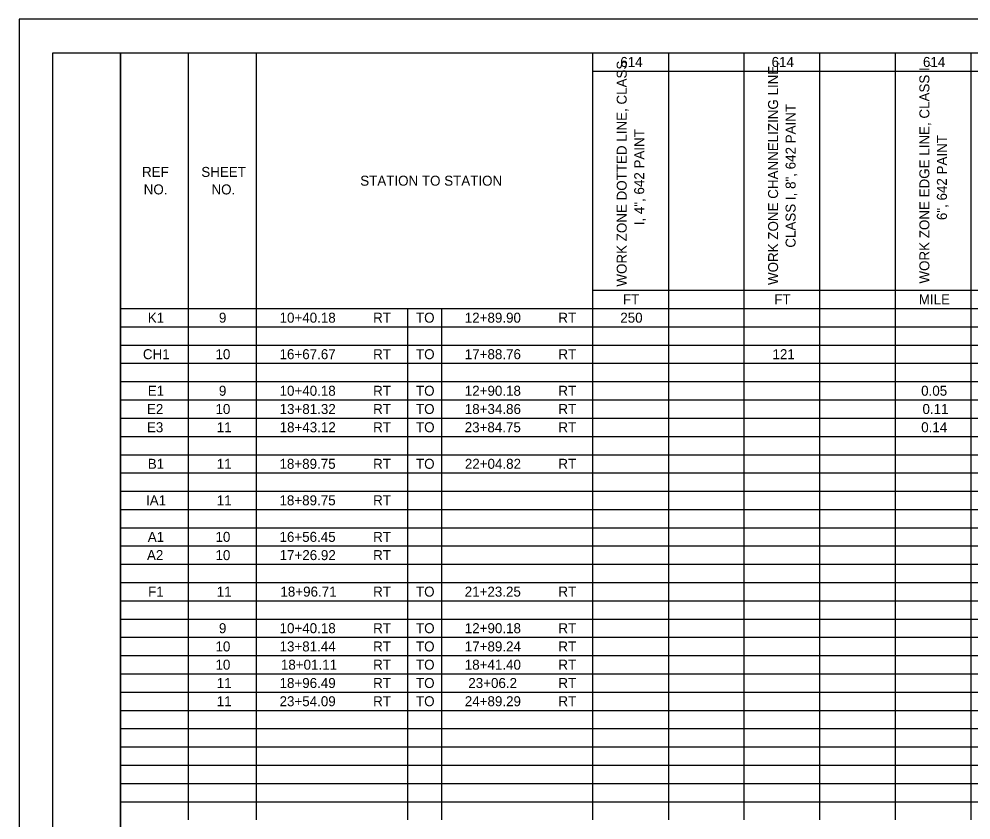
# Model space of a CAD drawing. Extents: x 0 to 34, y 0 to 22.
# Drawn here: x 0 to 14.09, y 10.15 to 22 of the extents above; entities that cross this region are included whole.
import ezdxf

# ---------------------------------------------------------------- set-up
doc = ezdxf.new("R2010")
doc.units = 0
for name, color, linetype in [('Default', 7, 'Continuous'), ('SH_Border', 7, 'Continuous'), ('SH_Cut_Line', 7, 'Continuous')]:
    doc.layers.add(name, color=color, linetype=linetype)

msp = doc.modelspace()

# ---------------------------------------------------------------- linework, layer by layer
at = {"layer": 'Default'}
for p, q in [((1.5, 21.5), (5.747, 21.5)), ((1.5, 21.5), (1.5, 21.23)), ((2.504, 21.5), (2.504, 21.23)), ((3.508, 21.5), (3.508, 21.23)), ((5.747, 21.5), (6.249, 21.5)), ((6.249, 21.5), (7.716, 21.5)), ((7.716, 21.5), (10.727, 21.5)), ((8.488, 21.5), (8.488, 21.23)), ((9.608, 21.5), (9.608, 21.23)), ((10.727, 21.5), (11.847, 21.5)), ((10.727, 21.5), (10.727, 21.23)), ((11.847, 21.5), (14.086, 21.5)), ((11.847, 21.5), (11.847, 21.23)), ((12.966, 21.5), (12.966, 21.23)), ((14.086, 21.5), (15.206, 21.5)), ((14.086, 21.5), (14.086, 21.23)), ((1.5, 21.23), (1.5, 20.959)), ((2.504, 21.23), (2.504, 20.959)), ((3.508, 21.23), (3.508, 20.959)), ((8.488, 21.23), (10.727, 21.23)), ((8.488, 21.23), (8.488, 20.959)), ((9.608, 21.23), (9.608, 20.959)), ((10.727, 21.23), (11.847, 21.23)), ((10.727, 21.23), (10.727, 20.959)), ((11.847, 21.23), (14.086, 21.23)), ((11.847, 21.23), (11.847, 20.959)), ((12.966, 21.23), (12.966, 20.959)), ((14.086, 21.23), (15.206, 21.23)), ((14.086, 21.23), (14.086, 20.959)), ((1.5, 20.959), (1.5, 20.689)), ((2.504, 20.959), (2.504, 20.689)), ((3.508, 20.959), (3.508, 20.689)), ((8.488, 20.959), (8.488, 20.689)), ((9.608, 20.959), (9.608, 20.689)), ((10.727, 20.959), (10.727, 20.689)), ((11.847, 20.959), (11.847, 20.689)), ((12.966, 20.959), (12.966, 20.689)), ((14.086, 20.959), (14.086, 20.689)), ((1.5, 20.689), (1.5, 20.419)), ((2.504, 20.689), (2.504, 20.419)), ((3.508, 20.689), (3.508, 20.419)), ((8.488, 20.689), (8.488, 20.419)), ((9.608, 20.689), (9.608, 20.419)), ((10.727, 20.689), (10.727, 20.419)), ((11.847, 20.689), (11.847, 20.419)), ((12.966, 20.689), (12.966, 20.419)), ((14.086, 20.689), (14.086, 20.419)), ((1.5, 20.419), (1.5, 20.149)), ((2.504, 20.419), (2.504, 20.149)), ((3.508, 20.419), (3.508, 20.149)), ((8.488, 20.419), (8.488, 20.149)), ((9.608, 20.419), (9.608, 20.149)), ((10.727, 20.419), (10.727, 20.149)), ((11.847, 20.419), (11.847, 20.149)), ((12.966, 20.419), (12.966, 20.149)), ((14.086, 20.419), (14.086, 20.149)), ((1.5, 20.149), (1.5, 19.878)), ((2.504, 20.149), (2.504, 19.878)), ((3.508, 20.149), (3.508, 19.878)), ((8.488, 20.149), (8.488, 19.878)), ((9.608, 20.149), (9.608, 19.878)), ((10.727, 20.149), (10.727, 19.878)), ((11.847, 20.149), (11.847, 19.878)), ((12.966, 20.149), (12.966, 19.878)), ((14.086, 20.149), (14.086, 19.878)), ((1.5, 19.878), (1.5, 19.608)), ((2.504, 19.878), (2.504, 19.608)), ((3.508, 19.878), (3.508, 19.608)), ((8.488, 19.878), (8.488, 19.608)), ((9.608, 19.878), (9.608, 19.608)), ((10.727, 19.878), (10.727, 19.608)), ((11.847, 19.878), (11.847, 19.608)), ((12.966, 19.878), (12.966, 19.608)), ((14.086, 19.878), (14.086, 19.608)), ((1.5, 19.608), (1.5, 19.068)), ((2.504, 19.608), (2.504, 19.068)), ((3.508, 19.608), (3.508, 19.068)), ((8.488, 19.608), (8.488, 19.068)), ((9.608, 19.608), (9.608, 19.068)), ((10.727, 19.608), (10.727, 19.068)), ((11.847, 19.608), (11.847, 19.068)), ((12.966, 19.608), (12.966, 19.068)), ((14.086, 19.608), (14.086, 19.068)), ((1.5, 19.068), (1.5, 18.257)), ((2.504, 19.068), (2.504, 18.257)), ((3.508, 19.068), (3.508, 18.257)), ((8.488, 19.068), (8.488, 18.257)), ((9.608, 19.068), (9.608, 18.257)), ((10.727, 19.068), (10.727, 18.257)), ((11.847, 19.068), (11.847, 18.257)), ((12.966, 19.068), (12.966, 18.257)), ((14.086, 19.068), (14.086, 18.257)), ((1.5, 18.257), (1.5, 17.987)), ((2.504, 18.257), (2.504, 17.987)), ((3.508, 18.257), (3.508, 17.987)), ((8.488, 18.257), (8.488, 17.987)), ((9.608, 18.257), (9.608, 17.987)), ((10.727, 18.257), (10.727, 17.987)), ((11.847, 18.257), (11.847, 17.987)), ((12.966, 18.257), (12.966, 17.987)), ((14.086, 18.257), (14.086, 17.987)), ((1.5, 17.987), (1.5, 17.446)), ((2.504, 17.987), (2.504, 17.446)), ((3.508, 17.987), (3.508, 17.446)), ((8.488, 17.987), (10.727, 17.987)), ((8.488, 17.987), (8.488, 17.446)), ((9.608, 17.987), (9.608, 17.446)), ((10.727, 17.987), (11.847, 17.987)), ((10.727, 17.987), (10.727, 17.446)), ((11.847, 17.987), (14.086, 17.987)), ((11.847, 17.987), (11.847, 17.446)), ((12.966, 17.987), (12.966, 17.446)), ((14.086, 17.987), (15.206, 17.987)), ((14.086, 17.987), (14.086, 17.446)), ((1.5, 17.716), (5.747, 17.716)), ((5.747, 17.716), (6.249, 17.716)), ((5.747, 17.716), (5.747, 17.446)), ((6.249, 17.716), (7.716, 17.716)), ((6.249, 17.716), (6.249, 17.446)), ((7.716, 17.716), (10.727, 17.716)), ((10.727, 17.716), (11.847, 17.716)), ((11.847, 17.716), (14.086, 17.716)), ((14.086, 17.716), (15.206, 17.716)), ((1.5, 17.446), (5.747, 17.446)), ((1.5, 17.446), (1.5, 17.176)), ((2.504, 17.446), (2.504, 17.176)), ((3.508, 17.446), (3.508, 17.176)), ((5.747, 17.446), (6.249, 17.446)), ((5.747, 17.446), (5.747, 17.176)), ((6.249, 17.446), (7.716, 17.446)), ((6.249, 17.446), (6.249, 17.176)), ((7.716, 17.446), (10.727, 17.446)), ((8.488, 17.446), (8.488, 17.176)), ((9.608, 17.446), (9.608, 17.176)), ((10.727, 17.446), (11.847, 17.446)), ((10.727, 17.446), (10.727, 17.176)), ((11.847, 17.446), (14.086, 17.446)), ((11.847, 17.446), (11.847, 17.176)), ((12.966, 17.446), (12.966, 17.176)), ((14.086, 17.446), (15.206, 17.446)), ((14.086, 17.446), (14.086, 17.176)), ((1.5, 17.176), (5.747, 17.176)), ((1.5, 17.176), (1.5, 16.095)), ((2.504, 17.176), (2.504, 16.095)), ((3.508, 17.176), (3.508, 16.095)), ((5.747, 17.176), (6.249, 17.176)), ((5.747, 17.176), (5.747, 16.095)), ((6.249, 17.176), (7.716, 17.176)), ((6.249, 17.176), (6.249, 16.095)), ((7.716, 17.176), (10.727, 17.176)), ((8.488, 17.176), (8.488, 16.095)), ((9.608, 17.176), (9.608, 16.095)), ((10.727, 17.176), (11.847, 17.176)), ((10.727, 17.176), (10.727, 16.095)), ((11.847, 17.176), (14.086, 17.176)), ((11.847, 17.176), (11.847, 16.095)), ((12.966, 17.176), (12.966, 16.095)), ((14.086, 17.176), (15.206, 17.176)), ((14.086, 17.176), (14.086, 16.095)), ((1.5, 16.906), (5.747, 16.906)), ((5.747, 16.906), (6.249, 16.906)), ((6.249, 16.906), (7.716, 16.906)), ((7.716, 16.906), (10.727, 16.906)), ((10.727, 16.906), (11.847, 16.906)), ((11.847, 16.906), (14.086, 16.906)), ((14.086, 16.906), (15.206, 16.906)), ((1.5, 16.635), (5.747, 16.635)), ((5.747, 16.635), (6.249, 16.635)), ((6.249, 16.635), (7.716, 16.635)), ((7.716, 16.635), (10.727, 16.635)), ((10.727, 16.635), (11.847, 16.635)), ((11.847, 16.635), (14.086, 16.635)), ((14.086, 16.635), (15.206, 16.635)), ((1.5, 16.365), (5.747, 16.365)), ((5.747, 16.365), (6.249, 16.365)), ((6.249, 16.365), (7.716, 16.365)), ((7.716, 16.365), (10.727, 16.365)), ((10.727, 16.365), (11.847, 16.365)), ((11.847, 16.365), (14.086, 16.365)), ((14.086, 16.365), (15.206, 16.365)), ((1.5, 16.095), (5.747, 16.095)), ((1.5, 16.095), (1.5, 15.825)), ((2.504, 16.095), (2.504, 15.825)), ((3.508, 16.095), (3.508, 15.825)), ((5.747, 16.095), (6.249, 16.095)), ((5.747, 16.095), (5.747, 15.825)), ((6.249, 16.095), (7.716, 16.095)), ((6.249, 16.095), (6.249, 15.825)), ((7.716, 16.095), (10.727, 16.095)), ((8.488, 16.095), (8.488, 15.825)), ((9.608, 16.095), (9.608, 15.825)), ((10.727, 16.095), (11.847, 16.095)), ((10.727, 16.095), (10.727, 15.825)), ((11.847, 16.095), (14.086, 16.095)), ((11.847, 16.095), (11.847, 15.825)), ((12.966, 16.095), (12.966, 15.825)), ((14.086, 16.095), (15.206, 16.095)), ((14.086, 16.095), (14.086, 15.825)), ((1.5, 15.825), (5.747, 15.825)), ((1.5, 15.825), (1.5, 15.284)), ((2.504, 15.825), (2.504, 15.284)), ((3.508, 15.825), (3.508, 15.284)), ((5.747, 15.825), (6.249, 15.825)), ((5.747, 15.825), (5.747, 15.284)), ((6.249, 15.825), (7.716, 15.825)), ((6.249, 15.825), (6.249, 15.284)), ((7.716, 15.825), (10.727, 15.825)), ((8.488, 15.825), (8.488, 15.284)), ((9.608, 15.825), (9.608, 15.284)), ((10.727, 15.825), (11.847, 15.825)), ((10.727, 15.825), (10.727, 15.284)), ((11.847, 15.825), (14.086, 15.825)), ((11.847, 15.825), (11.847, 15.284)), ((12.966, 15.825), (12.966, 15.284)), ((14.086, 15.825), (15.206, 15.825)), ((14.086, 15.825), (14.086, 15.284)), ((1.5, 15.554), (5.747, 15.554)), ((5.747, 15.554), (6.249, 15.554)), ((6.249, 15.554), (7.716, 15.554)), ((7.716, 15.554), (10.727, 15.554)), ((10.727, 15.554), (11.847, 15.554)), ((11.847, 15.554), (14.086, 15.554)), ((14.086, 15.554), (15.206, 15.554)), ((1.5, 15.284), (5.747, 15.284)), ((1.5, 15.284), (1.5, 14.744)), ((2.504, 15.284), (2.504, 14.744)), ((3.508, 15.284), (3.508, 14.744)), ((5.747, 15.284), (6.249, 15.284)), ((5.747, 15.284), (5.747, 14.744)), ((6.249, 15.284), (7.716, 15.284)), ((6.249, 15.284), (6.249, 14.744)), ((7.716, 15.284), (10.727, 15.284)), ((8.488, 15.284), (8.488, 14.744)), ((9.608, 15.284), (9.608, 14.744)), ((10.727, 15.284), (11.847, 15.284)), ((10.727, 15.284), (10.727, 14.744)), ((11.847, 15.284), (14.086, 15.284)), ((11.847, 15.284), (11.847, 14.744)), ((12.966, 15.284), (12.966, 14.744)), ((14.086, 15.284), (15.206, 15.284)), ((14.086, 15.284), (14.086, 14.744)), ((1.5, 15.014), (5.747, 15.014)), ((5.747, 15.014), (6.249, 15.014)), ((6.249, 15.014), (7.716, 15.014)), ((7.716, 15.014), (10.727, 15.014)), ((10.727, 15.014), (11.847, 15.014)), ((11.847, 15.014), (14.086, 15.014)), ((14.086, 15.014), (15.206, 15.014)), ((1.5, 14.744), (5.747, 14.744)), ((1.5, 14.744), (1.5, 14.473)), ((2.504, 14.744), (2.504, 14.473)), ((3.508, 14.744), (3.508, 14.473)), ((5.747, 14.744), (6.249, 14.744)), ((5.747, 14.744), (5.747, 14.473)), ((6.249, 14.744), (7.716, 14.744)), ((6.249, 14.744), (6.249, 14.473)), ((7.716, 14.744), (10.727, 14.744)), ((8.488, 14.744), (8.488, 14.473)), ((9.608, 14.744), (9.608, 14.473)), ((10.727, 14.744), (11.847, 14.744)), ((10.727, 14.744), (10.727, 14.473)), ((11.847, 14.744), (14.086, 14.744)), ((11.847, 14.744), (11.847, 14.473)), ((12.966, 14.744), (12.966, 14.473)), ((14.086, 14.744), (15.206, 14.744)), ((14.086, 14.744), (14.086, 14.473)), ((1.5, 14.473), (5.747, 14.473)), ((1.5, 14.473), (1.5, 13.933)), ((2.504, 14.473), (2.504, 13.933)), ((3.508, 14.473), (3.508, 13.933)), ((5.747, 14.473), (6.249, 14.473)), ((5.747, 14.473), (5.747, 13.933)), ((6.249, 14.473), (7.716, 14.473)), ((6.249, 14.473), (6.249, 13.933)), ((7.716, 14.473), (10.727, 14.473)), ((8.488, 14.473), (8.488, 13.933)), ((9.608, 14.473), (9.608, 13.933)), ((10.727, 14.473), (11.847, 14.473)), ((10.727, 14.473), (10.727, 13.933)), ((11.847, 14.473), (14.086, 14.473)), ((11.847, 14.473), (11.847, 13.933)), ((12.966, 14.473), (12.966, 13.933)), ((14.086, 14.473), (15.206, 14.473)), ((14.086, 14.473), (14.086, 13.933)), ((1.5, 14.203), (5.747, 14.203)), ((5.747, 14.203), (6.249, 14.203)), ((6.249, 14.203), (7.716, 14.203)), ((7.716, 14.203), (10.727, 14.203)), ((10.727, 14.203), (11.847, 14.203)), ((11.847, 14.203), (14.086, 14.203)), ((14.086, 14.203), (15.206, 14.203)), ((1.5, 13.933), (5.747, 13.933)), ((1.5, 13.933), (1.5, 13.663)), ((2.504, 13.933), (2.504, 13.663)), ((3.508, 13.933), (3.508, 13.663)), ((5.747, 13.933), (6.249, 13.933)), ((5.747, 13.933), (5.747, 13.663)), ((6.249, 13.933), (7.716, 13.933)), ((6.249, 13.933), (6.249, 13.663)), ((7.716, 13.933), (10.727, 13.933)), ((8.488, 13.933), (8.488, 13.663)), ((9.608, 13.933), (9.608, 13.663)), ((10.727, 13.933), (11.847, 13.933)), ((10.727, 13.933), (10.727, 13.663)), ((11.847, 13.933), (14.086, 13.933)), ((11.847, 13.933), (11.847, 13.663)), ((12.966, 13.933), (12.966, 13.663)), ((14.086, 13.933), (15.206, 13.933)), ((14.086, 13.933), (14.086, 13.663)), ((1.5, 13.663), (5.747, 13.663)), ((1.5, 13.663), (1.5, 12.852)), ((2.504, 13.663), (2.504, 12.852)), ((3.508, 13.663), (3.508, 12.852)), ((5.747, 13.663), (6.249, 13.663)), ((5.747, 13.663), (5.747, 12.852)), ((6.249, 13.663), (7.716, 13.663)), ((6.249, 13.663), (6.249, 12.852)), ((7.716, 13.663), (10.727, 13.663)), ((8.488, 13.663), (8.488, 12.852)), ((9.608, 13.663), (9.608, 12.852)), ((10.727, 13.663), (11.847, 13.663)), ((10.727, 13.663), (10.727, 12.852)), ((11.847, 13.663), (14.086, 13.663)), ((11.847, 13.663), (11.847, 12.852)), ((12.966, 13.663), (12.966, 12.852)), ((14.086, 13.663), (15.206, 13.663)), ((14.086, 13.663), (14.086, 12.852)), ((1.5, 13.392), (5.747, 13.392)), ((5.747, 13.392), (6.249, 13.392)), ((6.249, 13.392), (7.716, 13.392)), ((7.716, 13.392), (10.727, 13.392)), ((10.727, 13.392), (11.847, 13.392)), ((11.847, 13.392), (14.086, 13.392)), ((14.086, 13.392), (15.206, 13.392)), ((1.5, 13.122), (5.747, 13.122)), ((5.747, 13.122), (6.249, 13.122)), ((6.249, 13.122), (7.716, 13.122)), ((7.716, 13.122), (10.727, 13.122)), ((10.727, 13.122), (11.847, 13.122)), ((11.847, 13.122), (14.086, 13.122)), ((14.086, 13.122), (15.206, 13.122)), ((1.5, 12.852), (5.747, 12.852)), ((1.5, 12.852), (1.5, 12.311)), ((2.504, 12.852), (2.504, 12.311)), ((3.508, 12.852), (3.508, 12.311)), ((5.747, 12.852), (6.249, 12.852)), ((5.747, 12.852), (5.747, 12.311)), ((6.249, 12.852), (7.716, 12.852)), ((6.249, 12.852), (6.249, 12.311)), ((7.716, 12.852), (10.727, 12.852)), ((8.488, 12.852), (8.488, 12.311)), ((9.608, 12.852), (9.608, 12.311)), ((10.727, 12.852), (11.847, 12.852)), ((10.727, 12.852), (10.727, 12.311)), ((11.847, 12.852), (14.086, 12.852)), ((11.847, 12.852), (11.847, 12.311)), ((12.966, 12.852), (12.966, 12.311)), ((14.086, 12.852), (15.206, 12.852)), ((14.086, 12.852), (14.086, 12.311)), ((1.5, 12.582), (5.747, 12.582)), ((5.747, 12.582), (6.249, 12.582)), ((6.249, 12.582), (7.716, 12.582)), ((7.716, 12.582), (10.727, 12.582)), ((10.727, 12.582), (11.847, 12.582)), ((11.847, 12.582), (14.086, 12.582)), ((14.086, 12.582), (15.206, 12.582)), ((1.5, 12.311), (5.747, 12.311)), ((1.5, 12.311), (1.5, 11.501)), ((2.504, 12.311), (2.504, 11.501)), ((3.508, 12.311), (3.508, 11.501)), ((5.747, 12.311), (6.249, 12.311)), ((5.747, 12.311), (5.747, 11.501)), ((6.249, 12.311), (7.716, 12.311)), ((6.249, 12.311), (6.249, 11.501)), ((7.716, 12.311), (10.727, 12.311)), ((8.488, 12.311), (8.488, 11.501)), ((9.608, 12.311), (9.608, 11.501)), ((10.727, 12.311), (11.847, 12.311)), ((10.727, 12.311), (10.727, 11.501)), ((11.847, 12.311), (14.086, 12.311)), ((11.847, 12.311), (11.847, 11.501)), ((12.966, 12.311), (12.966, 11.501)), ((14.086, 12.311), (15.206, 12.311)), ((14.086, 12.311), (14.086, 11.501)), ((1.5, 12.041), (5.747, 12.041)), ((5.747, 12.041), (6.249, 12.041)), ((6.249, 12.041), (7.716, 12.041)), ((7.716, 12.041), (10.727, 12.041)), ((10.727, 12.041), (11.847, 12.041)), ((11.847, 12.041), (14.086, 12.041)), ((14.086, 12.041), (15.206, 12.041)), ((1.5, 11.771), (5.747, 11.771)), ((5.747, 11.771), (6.249, 11.771)), ((6.249, 11.771), (7.716, 11.771)), ((7.716, 11.771), (10.727, 11.771)), ((10.727, 11.771), (11.847, 11.771)), ((11.847, 11.771), (14.086, 11.771)), ((14.086, 11.771), (15.206, 11.771)), ((1.5, 11.501), (5.747, 11.501)), ((1.5, 11.501), (1.5, 10.96)), ((2.504, 11.501), (2.504, 10.96)), ((3.508, 11.501), (3.508, 10.96)), ((5.747, 11.501), (6.249, 11.501)), ((5.747, 11.501), (5.747, 10.96)), ((6.249, 11.501), (7.716, 11.501)), ((6.249, 11.501), (6.249, 10.96)), ((7.716, 11.501), (10.727, 11.501)), ((8.488, 11.501), (8.488, 10.96)), ((9.608, 11.501), (9.608, 10.96)), ((10.727, 11.501), (11.847, 11.501)), ((10.727, 11.501), (10.727, 10.96)), ((11.847, 11.501), (14.086, 11.501)), ((11.847, 11.501), (11.847, 10.96)), ((12.966, 11.501), (12.966, 10.96)), ((14.086, 11.501), (15.206, 11.501)), ((14.086, 11.501), (14.086, 10.96)), ((1.5, 11.23), (5.747, 11.23)), ((5.747, 11.23), (6.249, 11.23)), ((6.249, 11.23), (7.716, 11.23)), ((7.716, 11.23), (10.727, 11.23)), ((10.727, 11.23), (11.847, 11.23)), ((11.847, 11.23), (14.086, 11.23)), ((14.086, 11.23), (15.206, 11.23)), ((1.5, 10.96), (5.747, 10.96)), ((1.5, 10.96), (1.5, 10.149)), ((2.504, 10.96), (2.504, 10.149)), ((3.508, 10.96), (3.508, 10.149)), ((5.747, 10.96), (6.249, 10.96)), ((5.747, 10.96), (5.747, 10.149)), ((6.249, 10.96), (7.716, 10.96)), ((6.249, 10.96), (6.249, 10.149)), ((7.716, 10.96), (10.727, 10.96)), ((8.488, 10.96), (8.488, 10.149)), ((9.608, 10.96), (9.608, 10.149)), ((10.727, 10.96), (11.847, 10.96)), ((10.727, 10.96), (10.727, 10.149)), ((11.847, 10.96), (14.086, 10.96)), ((11.847, 10.96), (11.847, 10.149)), ((12.966, 10.96), (12.966, 10.149)), ((14.086, 10.96), (15.206, 10.96)), ((14.086, 10.96), (14.086, 10.149)), ((1.5, 10.69), (5.747, 10.69)), ((5.747, 10.69), (6.249, 10.69)), ((6.249, 10.69), (7.716, 10.69)), ((7.716, 10.69), (10.727, 10.69)), ((10.727, 10.69), (11.847, 10.69)), ((11.847, 10.69), (14.086, 10.69)), ((14.086, 10.69), (15.206, 10.69)), ((1.5, 10.42), (5.747, 10.42)), ((5.747, 10.42), (6.249, 10.42)), ((6.249, 10.42), (7.716, 10.42)), ((7.716, 10.42), (10.727, 10.42)), ((10.727, 10.42), (11.847, 10.42)), ((11.847, 10.42), (14.086, 10.42)), ((14.086, 10.42), (15.206, 10.42))]:
    msp.add_line(p, q, dxfattribs=at)
at = {"layer": 'SH_Border'}
for points in [[(0.5, 21.5), (1.5, 21.5), (1.5, 0.5), (0.5, 0.5)], [(1.5, 21.5), (33.5, 21.5), (33.5, 0.5), (1.5, 0.5)]]:
    msp.add_lwpolyline(points, close=True, dxfattribs=at)
at = {"layer": 'SH_Cut_Line'}
msp.add_lwpolyline([(0, 0), (34, 0), (34, 22), (0, 22)], close=True, dxfattribs=at)

# ---------------------------------------------------------------- texts
at = {"layer": 'Default'}
for s, p in [('614', (8.897, 21.291)), ('614', (11.136, 21.291)), ('614', (13.376, 21.291)), ('REF', (1.82, 19.664)), ('SHEET', (2.697, 19.664)), ('STATION TO STATION', (5.049, 19.534)), ('NO.', (1.845, 19.405)), ('NO.', (2.848, 19.405)), ('FT', (8.936, 17.778)), ('FT', (11.175, 17.778)), ('MILE', (13.314, 17.778)), ('K1', (1.905, 17.507)), ('9', (2.958, 17.507)), ('10+40.18', (3.855, 17.507)), ('RT', (5.24, 17.507)), ('TO', (5.874, 17.507)), ('12+89.90', (6.596, 17.507)), ('RT', (7.981, 17.507)), ('250', (8.897, 17.507)), ('CH1', (1.833, 16.967)), ('10', (2.907, 16.967)), ('16+67.67', (3.855, 16.967)), ('RT', (5.24, 16.967)), ('TO', (5.874, 16.967)), ('17+88.76', (6.596, 16.967)), ('RT', (7.981, 16.967)), ('121', (11.149, 16.967)), ('E1', (1.905, 16.426)), ('9', (2.958, 16.426)), ('10+40.18', (3.855, 16.426)), ('RT', (5.24, 16.426)), ('TO', (5.874, 16.426)), ('12+90.18', (6.596, 16.426)), ('RT', (7.981, 16.426)), ('0.05', (13.349, 16.426)), ('E2', (1.893, 16.156)), ('10', (2.907, 16.156)), ('13+81.32', (3.856, 16.156)), ('RT', (5.24, 16.156)), ('TO', (5.874, 16.156)), ('18+34.86', (6.596, 16.156)), ('RT', (7.981, 16.156)), ('0.11', (13.369, 16.156)), ('E3', (1.892, 15.886)), ('11', (2.926, 15.886)), ('18+43.12', (3.856, 15.886)), ('RT', (5.24, 15.886)), ('TO', (5.874, 15.886)), ('23+84.75', (6.595, 15.886)), ('RT', (7.981, 15.886)), ('0.14', (13.35, 15.886)), ('18+89.75', (3.854, 15.345)), ('TO', (5.874, 15.345)), ('22+04.82', (6.597, 15.345)), ('B1', (1.905, 15.345)), ('11', (2.926, 15.345)), ('RT', (5.24, 15.345)), ('RT', (7.981, 15.345)), ('IA1', (1.879, 14.805)), ('11', (2.926, 14.805)), ('18+89.75', (3.854, 14.805)), ('RT', (5.24, 14.805)), ('A1', (1.905, 14.264)), ('10', (2.907, 14.264)), ('16+56.45', (3.854, 14.264)), ('RT', (5.24, 14.264)), ('A2', (1.893, 13.994)), ('10', (2.907, 13.994)), ('17+26.92', (3.856, 13.994)), ('RT', (5.24, 13.994)), ('F1', (1.91, 13.454)), ('11', (2.926, 13.454)), ('18+96.71', (3.868, 13.454)), ('RT', (5.24, 13.454)), ('TO', (5.874, 13.454)), ('21+23.25', (6.595, 13.454)), ('RT', (7.981, 13.454)), ('9', (2.958, 12.913)), ('10+40.18', (3.855, 12.913)), ('RT', (5.24, 12.913)), ('TO', (5.874, 12.913)), ('12+90.18', (6.596, 12.913)), ('RT', (7.981, 12.913)), ('10', (2.907, 12.643)), ('13+81.44', (3.855, 12.643)), ('RT', (5.24, 12.643)), ('TO', (5.874, 12.643)), ('17+89.24', (6.596, 12.643)), ('RT', (7.981, 12.643)), ('10', (2.907, 12.373)), ('18+01.11', (3.875, 12.373)), ('RT', (5.24, 12.373)), ('TO', (5.874, 12.373)), ('18+41.40', (6.596, 12.373)), ('RT', (7.981, 12.373)), ('11', (2.926, 12.102)), ('18+96.49', (3.855, 12.102)), ('RT', (5.24, 12.102)), ('TO', (5.874, 12.102)), ('23+06.2', (6.648, 12.102)), ('RT', (7.981, 12.102)), ('11', (2.926, 11.832)), ('23+54.09', (3.855, 11.832)), ('RT', (5.24, 11.832)), ('TO', (5.874, 11.832)), ('24+89.29', (6.596, 11.832)), ('RT', (7.981, 11.832))]:
    msp.add_text(s, height=0.148, dxfattribs=at).set_placement(p)
for s, p in [('WORK ZONE DOTTED LINE, CLASS ', (8.992, 18.041)), ('WORK ZONE CHANNELIZING LINE, ', (11.232, 18.065)), ('WORK ZONE EDGE LINE, CLASS I, ', (13.471, 18.086)), ('CLASS I, 8", 642 PAINT', (11.491, 18.617)), ('I, 4", 642 PAINT', (9.251, 18.948)), ('6", 642 PAINT', (13.73, 19.025))]:
    msp.add_text(s, height=0.148, rotation=90, dxfattribs=at).set_placement(p)

doc.saveas('drawing.dxf')
